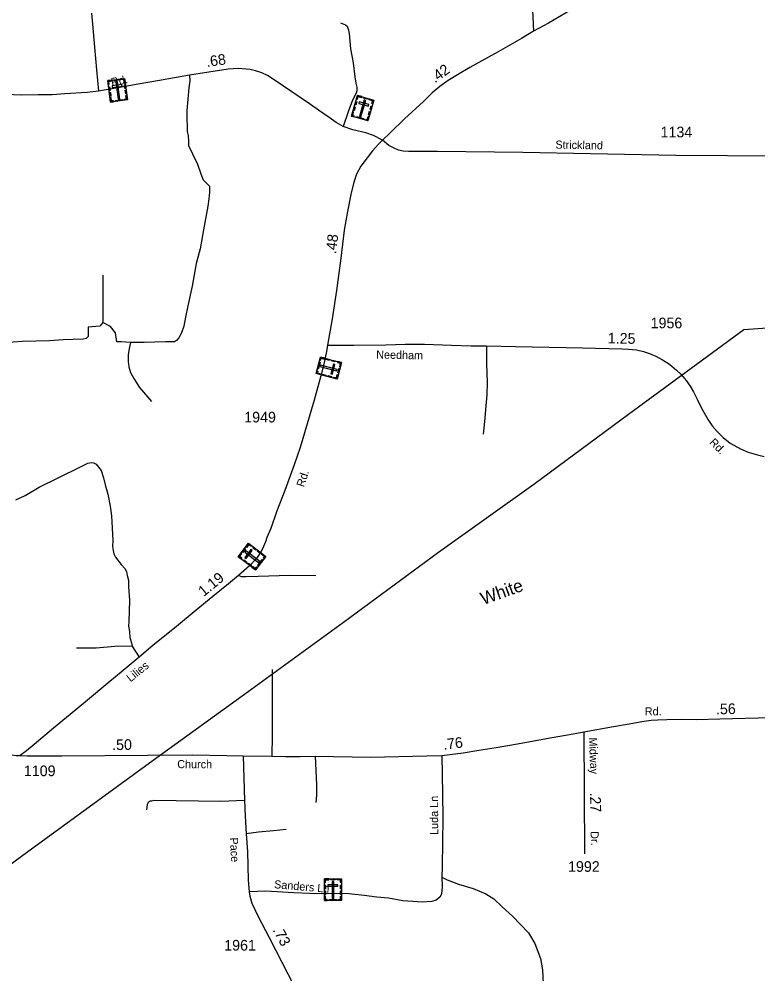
# Model space of a CAD drawing. Extents: x 2220236 to 2384410, y 720751 to 894131.
# Drawn here: x 2264356 to 2273033, y 747219 to 758435 of the extents above; entities that cross this region are included whole.
import ezdxf

# ---------------------------------------------------------------- set-up
doc = ezdxf.new("R2010")
doc.units = 0
doc.layers.add('Default', color=7, linetype='Continuous')

msp = doc.modelspace()

# ---------------------------------------------------------------- linework, layer by layer
at = {"layer": 'Default'}
for p, q in [((2265340, 755428), (2265340, 754870)), ((2270990, 750061), (2270997, 748629))]:
    msp.add_line(p, q, dxfattribs=at)
for points in [[(2273900, 762117), (2273776, 762003), (2273579, 761804), (2273435, 761662), (2273296, 761515), (2273178, 761369), (2273059, 761201), (2272866, 760933), (2272513, 760409), (2272363, 760190), (2272228, 759991), (2272062, 759755), (2271973, 759635), (2271812, 759413), (2271662, 759231), (2271443, 759002), (2271398, 758959), (2271277, 758844), (2271156, 758745), (2270989, 758635), (2270773, 758503), (2270574, 758389), (2270399, 758294)], [(2270379, 758707), (2270399, 758294)], [(2265205, 758504), (2265216, 758375), (2265242, 758107), (2265266, 757838), (2265287, 757589)], [(2268132, 758390), (2268191, 758367), (2268209, 758353), (2268226, 758303), (2268231, 758266), (2268249, 758087), (2268280, 757922), (2268299, 757755), (2268309, 757683), (2268322, 757637), (2268322, 757592), (2268311, 757557), (2268270, 757482), (2268220, 757345), (2268163, 757175)], [(2270399, 758294), (2270256, 758206), (2269981, 758049), (2269792, 757945), (2269651, 757865), (2269504, 757780), (2269394, 757713), (2269296, 757643), (2269207, 757567), (2269104, 757467), (2268881, 757262), (2268715, 757098), (2268624, 757012)], [(2268624, 757012), (2268520, 757067), (2268428, 757100), (2268275, 757135), (2268163, 757175), (2268081, 757221), (2267997, 757279), (2267872, 757364), (2267777, 757432), (2267341, 757730), (2267273, 757774), (2267206, 757803), (2267132, 757829), (2267070, 757844), (2266930, 757854), (2266813, 757845), (2266357, 757778), (2266004, 757715), (2265754, 757672), (2265559, 757635), (2265287, 757589)], [(2266357, 757778), (2266360, 757708), (2266351, 757626), (2266336, 757495), (2266327, 757363), (2266325, 757277), (2266329, 757164), (2266331, 757114), (2266342, 757068), (2266346, 756997), (2266346, 756952), (2266393, 756851), (2266452, 756729), (2266489, 756616), (2266519, 756546), (2266556, 756506), (2266590, 756474), (2266593, 756456), (2266593, 756402), (2266585, 756323), (2266571, 756238), (2266520, 755960), (2266481, 755737), (2266437, 755564), (2266388, 755296), (2266336, 755068), (2266310, 754933), (2266289, 754826), (2266262, 754751), (2266232, 754692), (2266206, 754659), (2266181, 754642), (2266075, 754643), (2265823, 754635), (2265663, 754635)], [(2265287, 757589), (2265157, 757571), (2264894, 757556), (2264746, 757546), (2264580, 757544), (2264388, 757542), (2264086, 757555), (2263948, 757565), (2263767, 757588), (2263593, 757624), (2263167, 757725)], [(2268624, 757012), (2268576, 756965), (2268506, 756888), (2268370, 756709), (2268317, 756613), (2268288, 756519), (2268253, 756375), (2268213, 756174), (2268175, 755956), (2268134, 755628), (2268084, 755245), (2268031, 754915), (2267979, 754606)], [(2273283, 756826), (2272070, 756832), (2271065, 756852), (2270273, 756869), (2269270, 756880), (2269034, 756880), (2268930, 756880), (2268867, 756883), (2268813, 756896), (2268761, 756917), (2268699, 756952), (2268624, 757012)], [(2296526, 756314), (2294600, 756208), (2292309, 756063), (2290035, 755921), (2287749, 755780), (2285466, 755635), (2283160, 755491), (2281790, 755396), (2279029, 755228), (2276729, 755065), (2274892, 754928), (2272866, 754783), (2271512, 753789), (2270402, 752966), (2269282, 752170), (2268166, 751348), (2267047, 750534), (2265929, 749726), (2264444, 748641), (2263328, 747822), (2262406, 747872), (2261484, 747927), (2260116, 748002), (2259542, 748037)], [(2265340, 754870), (2265305, 754827), (2265166, 754817), (2265166, 754734), (2265166, 754705), (2265145, 754681), (2265108, 754675), (2264873, 754667), (2264713, 754657), (2264393, 754649), (2264285, 754638), (2264210, 754627), (2264110, 754614)], [(2265663, 754635), (2265555, 754644), (2265502, 754643), (2265489, 754750), (2265428, 754822), (2265340, 754870)], [(2265663, 754635), (2265648, 754565), (2265638, 754493), (2265635, 754413), (2265646, 754351), (2265664, 754285), (2265705, 754214), (2265768, 754108), (2265909, 753942)], [(2267979, 754606), (2268287, 754605), (2268663, 754609), (2268891, 754616), (2269117, 754616), (2269435, 754606), (2269666, 754598), (2269844, 754595), (2270187, 754589), (2270974, 754572), (2271433, 754561), (2271513, 754559), (2271606, 754548), (2271691, 754530), (2271761, 754507), (2271834, 754476), (2271914, 754432), (2271993, 754380), (2272075, 754311), (2272130, 754259), (2272189, 754189), (2272238, 754122), (2272277, 754055), (2272319, 753970), (2272369, 753866), (2272449, 753729), (2272495, 753659), (2272554, 753589), (2272625, 753520), (2272707, 753453), (2272829, 753386), (2272917, 753349), (2273029, 753315), (2273107, 753298)], [(2267979, 754606), (2267966, 754530), (2267933, 754380), (2267901, 754243), (2267820, 753960), (2267656, 753404), (2267588, 753198), (2267478, 752899), (2267378, 752647), (2267313, 752452), (2267267, 752347), (2267248, 752293), (2267228, 752238), (2267200, 752180), (2267143, 752099), (2267062, 752011), (2266932, 751900), (2266814, 751802), (2266632, 751654), (2266437, 751491), (2266203, 751300), (2265927, 751077), (2265765, 750939), (2265555, 750762), (2265421, 750653), (2265135, 750415), (2264955, 750266), (2264758, 750105), (2264531, 749914), (2264441, 749840), (2264369, 749784)], [(2269844, 754595), (2269847, 754385), (2269855, 754169), (2269850, 754022), (2269836, 753892), (2269823, 753707), (2269806, 753558)], [(2264317, 752787), (2264426, 752839), (2264593, 752937), (2265061, 753168), (2265162, 753219), (2265202, 753225), (2265230, 753222), (2265262, 753206), (2265321, 753131), (2265346, 753047), (2265367, 752963), (2265398, 752855), (2265427, 752714), (2265440, 752598), (2265455, 752310), (2265453, 752238), (2265460, 752194), (2265468, 752152), (2265489, 752115), (2265553, 752029), (2265596, 751982), (2265618, 751944), (2265625, 751900), (2265641, 751844), (2265642, 751764), (2265653, 751610), (2265647, 751480), (2265644, 751357), (2265640, 751304), (2265651, 751241), (2265657, 751171), (2265674, 751109), (2265682, 751069)], [(2267842, 751894), (2267537, 751898), (2267163, 751887), (2267023, 751884), (2266966, 751882), (2266932, 751900)], [(2265682, 751069), (2265480, 751063), (2265261, 751047), (2265031, 751047)], [(2265682, 751069), (2265707, 751029), (2265738, 750984), (2265765, 750939)], [(2267327, 750794), (2267327, 750248), (2267327, 750023), (2267326, 749777)], [(2270990, 750061), (2271337, 750124), (2271519, 750157), (2271671, 750182), (2271781, 750198), (2271858, 750203), (2271963, 750206), (2272130, 750211), (2272314, 750206), (2272587, 750214), (2273186, 750230), (2273451, 750237), (2273798, 750248), (2273960, 750245)], [(2266988, 749779), (2267326, 749777), (2267483, 749774), (2267655, 749774), (2267833, 749776), (2268482, 749766), (2269143, 749779), (2269321, 749785), (2269570, 749816), (2269755, 749846), (2269959, 749879), (2270209, 749920), (2270595, 749993), (2270886, 750042), (2270990, 750061)], [(2263347, 749940), (2263491, 749917), (2263644, 749890), (2263923, 749843), (2264141, 749805), (2264293, 749789), (2264322, 749785), (2264369, 749784)], [(2264369, 749784), (2264449, 749779), (2264858, 749779), (2265864, 749790), (2266394, 749793), (2266797, 749785), (2266988, 749779)], [(2266988, 749779), (2267003, 749254), (2267011, 749071), (2267023, 748865), (2267040, 748657), (2267047, 748321), (2267056, 748184), (2267065, 748133), (2267089, 748051), (2267161, 747900), (2267292, 747646), (2267441, 747358), (2267588, 747074), (2267665, 746912), (2267728, 746769), (2267759, 746693), (2267783, 746605), (2267797, 746507), (2267804, 746324), (2267810, 746072)], [(2267833, 749776), (2267847, 749438), (2267848, 749318), (2267839, 749232)], [(2269321, 749785), (2269329, 749336), (2269332, 749048), (2269325, 748485), (2269320, 748357)], [(2267003, 749254), (2266725, 749246), (2265939, 749254), (2265911, 749248), (2265895, 749248), (2265870, 749232), (2265858, 749208), (2265852, 749146)], [(2267491, 748916), (2267343, 748899), (2267166, 748882), (2267023, 748865)], [(2269320, 748357), (2269323, 748249), (2269320, 748189), (2269312, 748147), (2269296, 748119), (2269255, 748084), (2269205, 748068), (2269089, 748061), (2268979, 748068), (2268863, 748078), (2268695, 748107), (2268557, 748122), (2268407, 748140), (2268229, 748159), (2268085, 748165), (2267919, 748161), (2267767, 748164), (2267583, 748172), (2267255, 748191), (2267056, 748184)], [(2269320, 748357), (2269384, 748325), (2269517, 748273), (2269689, 748224), (2269838, 748160), (2269930, 748102), (2270031, 748007), (2270150, 747899), (2270338, 747701), (2270413, 747575), (2270481, 747398), (2270502, 747266), (2270509, 747101), (2270515, 746885), (2270511, 746325), (2270522, 746227), (2270522, 746147), (2270515, 746073)]]:
    msp.add_lwpolyline(points, dxfattribs=at)
for points in [[(2265398, 757712), (2265595, 757738), (2265629, 757486), (2265431, 757460)], [(2265404, 757669), (2265415, 757671), (2265411, 757703), (2265451, 757708), (2265449, 757719), (2265398, 757712)], [(2265447, 757650), (2265450, 757631), (2265567, 757647), (2265564, 757665)], [(2265471, 757722), (2265523, 757729), (2265524, 757717), (2265473, 757710)], [(2265510, 757697), (2265491, 757695), (2265518, 757494), (2265537, 757496)], [(2265601, 757695), (2265590, 757694), (2265586, 757726), (2265545, 757720), (2265544, 757731), (2265595, 757738)], [(2265599, 757621), (2265594, 757664), (2265605, 757666), (2265611, 757623)], [(2265413, 757596), (2265408, 757639), (2265419, 757640), (2265425, 757597)], [(2265422, 757529), (2265417, 757572), (2265428, 757573), (2265433, 757530)], [(2265596, 757481), (2265594, 757493), (2265616, 757496), (2265611, 757536), (2265622, 757537), (2265629, 757486)], [(2265608, 757556), (2265602, 757599), (2265614, 757600), (2265619, 757557)], [(2268331, 757539), (2268522, 757484), (2268452, 757239), (2268260, 757294)], [(2268319, 757497), (2268329, 757494), (2268338, 757525), (2268377, 757514), (2268380, 757524), (2268331, 757539)], [(2265464, 757464), (2265463, 757475), (2265441, 757473), (2265436, 757513), (2265425, 757511), (2265431, 757460)], [(2265487, 757479), (2265571, 757490), (2265572, 757478), (2265488, 757467)], [(2268298, 757426), (2268310, 757467), (2268321, 757464), (2268309, 757422)], [(2268351, 757462), (2268346, 757444), (2268459, 757412), (2268464, 757430)], [(2268427, 757480), (2268409, 757486), (2268354, 757291), (2268371, 757285)], [(2268402, 757518), (2268452, 757504), (2268448, 757493), (2268399, 757507)], [(2268510, 757442), (2268499, 757445), (2268508, 757476), (2268469, 757487), (2268472, 757498), (2268522, 757484)], [(2268479, 757375), (2268491, 757417), (2268502, 757413), (2268490, 757372)], [(2268292, 757285), (2268295, 757296), (2268274, 757302), (2268285, 757341), (2268275, 757344), (2268260, 757294)], [(2268280, 757361), (2268292, 757403), (2268303, 757399), (2268291, 757358)], [(2268461, 757312), (2268473, 757353), (2268484, 757350), (2268472, 757308)], [(2268319, 757289), (2268400, 757266), (2268397, 757255), (2268316, 757278)], [(2268420, 757248), (2268423, 757259), (2268444, 757253), (2268455, 757292), (2268466, 757289), (2268452, 757239)], [(2268141, 754400), (2268091, 754207), (2267845, 754272), (2267895, 754464)], [(2267892, 754406), (2267870, 754324), (2267859, 754327), (2267881, 754409)], [(2267887, 754432), (2267898, 754429), (2267903, 754451), (2267942, 754440), (2267945, 754451), (2267895, 754464)], [(2267963, 754447), (2268005, 754436), (2268002, 754425), (2267960, 754436)], [(2268028, 754430), (2268070, 754419), (2268067, 754408), (2268025, 754419)], [(2268099, 754411), (2268097, 754400), (2268128, 754392), (2268117, 754352), (2268128, 754350), (2268141, 754400)], [(2267853, 754304), (2267864, 754301), (2267858, 754280), (2267898, 754269), (2267895, 754259), (2267845, 754272)], [(2268085, 754302), (2268090, 754320), (2267894, 754371), (2267889, 754353)], [(2268065, 754378), (2268047, 754382), (2268017, 754268), (2268035, 754264)], [(2268123, 754328), (2268109, 754278), (2268098, 754281), (2268111, 754331)], [(2267917, 754264), (2267959, 754253), (2267956, 754242), (2267914, 754253)], [(2267981, 754248), (2268023, 754237), (2268020, 754226), (2267978, 754237)], [(2268049, 754218), (2268052, 754229), (2268083, 754221), (2268093, 754260), (2268104, 754257), (2268091, 754207)], [(2266929, 752119), (2267049, 752278), (2267253, 752124), (2267132, 751965)], [(2267084, 752251), (2267077, 752242), (2267052, 752262), (2267027, 752229), (2267018, 752236), (2267050, 752278)], [(2266964, 752093), (2266971, 752102), (2266945, 752121), (2266970, 752153), (2266961, 752160), (2266929, 752119)], [(2266974, 752178), (2267005, 752219), (2267014, 752212), (2266983, 752171)], [(2267018, 752188), (2267007, 752173), (2267169, 752051), (2267180, 752066)], [(2267008, 752110), (2267023, 752099), (2267094, 752193), (2267079, 752204)], [(2267135, 752198), (2267101, 752224), (2267108, 752234), (2267142, 752207)], [(2267188, 752159), (2267153, 752185), (2267160, 752194), (2267195, 752168)], [(2267233, 752098), (2267223, 752105), (2267237, 752122), (2267204, 752146), (2267211, 752155), (2267253, 752124)], [(2267023, 752048), (2266989, 752074), (2266995, 752083), (2267030, 752057)], [(2267077, 752007), (2267042, 752033), (2267049, 752043), (2267084, 752016)], [(2267158, 752018), (2267209, 752086), (2267218, 752079), (2267167, 752011)], [(2267152, 751992), (2267143, 751999), (2267130, 751981), (2267098, 752005), (2267091, 751997), (2267132, 751965)], [(2267942, 748335), (2268142, 748335), (2268141, 748080), (2267942, 748080)], [(2267942, 748292), (2267954, 748292), (2267954, 748324), (2267994, 748324), (2267994, 748335), (2267942, 748335)], [(2268017, 748335), (2268068, 748335), (2268068, 748323), (2268017, 748323)], [(2268142, 748291), (2268130, 748291), (2268130, 748323), (2268090, 748324), (2268090, 748335), (2268142, 748335)], [(2267942, 748217), (2267942, 748261), (2267954, 748261), (2267954, 748217)], [(2267983, 748267), (2267983, 748248), (2268101, 748248), (2268101, 748267)], [(2268051, 748305), (2268033, 748305), (2268032, 748103), (2268051, 748103)], [(2268130, 748218), (2268130, 748262), (2268141, 748262), (2268141, 748218)], [(2267942, 748150), (2267942, 748194), (2267954, 748194), (2267954, 748150)], [(2267975, 748080), (2267975, 748092), (2267953, 748092), (2267953, 748132), (2267942, 748132), (2267942, 748080)], [(2268108, 748080), (2268108, 748092), (2268130, 748092), (2268130, 748132), (2268141, 748132), (2268141, 748080)], [(2268130, 748152), (2268130, 748196), (2268141, 748196), (2268141, 748152)], [(2268000, 748092), (2268084, 748092), (2268084, 748080), (2268000, 748080)]]:
    msp.add_lwpolyline(points, close=True, dxfattribs=at)

# ---------------------------------------------------------------- texts
for s, height, rotation, p in [('.68', 125, 8.3682, (2266562, 757871)), ('.42', 125, 35.6452, (2269239, 757679)), ('Rd.', 95, 10.9437, (2265445, 757646)), ('Strickland', 95, 358.892, (2270654, 756914)), ('.48', 125, 82.8918, (2268077, 755670)), ('1.25', 125, 358.8306, (2271269, 754626)), ('Needham', 95, 358.848, (2268549, 754448)), ('Rd.', 95, 314.9927, (2272456, 753455)), ('Rd.', 95, 71.5451, (2267700, 752931)), ('1.19', 125, 39.2525, (2266523, 751645)), ('White', 150, 19.601, (2269807, 751551)), ('Lilies', 95, 39.1332, (2265665, 750642)), ('Rd.', 95, 0.6103, (2271705, 750255)), ('.56', 125, 1.3907, (2272542, 750267)), ('.50', 125, 0.64, (2265449, 749848)), ('.76', 125, 6.9928, (2269343, 749851)), ('Midway', 95, 272.0671, (2271049, 749995)), ('Church', 95, 359.6892, (2266213, 749636)), ('Luda Ln', 95, 90.2358, (2269278, 748852)), ('.27', 125, 272.0671, (2271060, 749347)), ('Pace', 95, 273.0882, (2266831, 748819)), ('Dr.', 95, 272.0671, (2271067, 748894)), ('Sanders Ln', 95, 355.1488, (2267348, 748226)), ('.73', 125, 298.4086, (2267331, 747735))]:
    msp.add_text(s, height=height, rotation=rotation, dxfattribs=at).set_placement(p)
for s, p in [('1134', (2271890, 757046)), ('1956', (2271773, 754803)), ('1949', (2267000, 753697)), ('1109', (2264412, 749542)), ('1992', (2270803, 748418)), ('1961', (2266765, 747493))]:
    msp.add_text(s, height=125, dxfattribs=at).set_placement(p)

doc.saveas('drawing.dxf')
